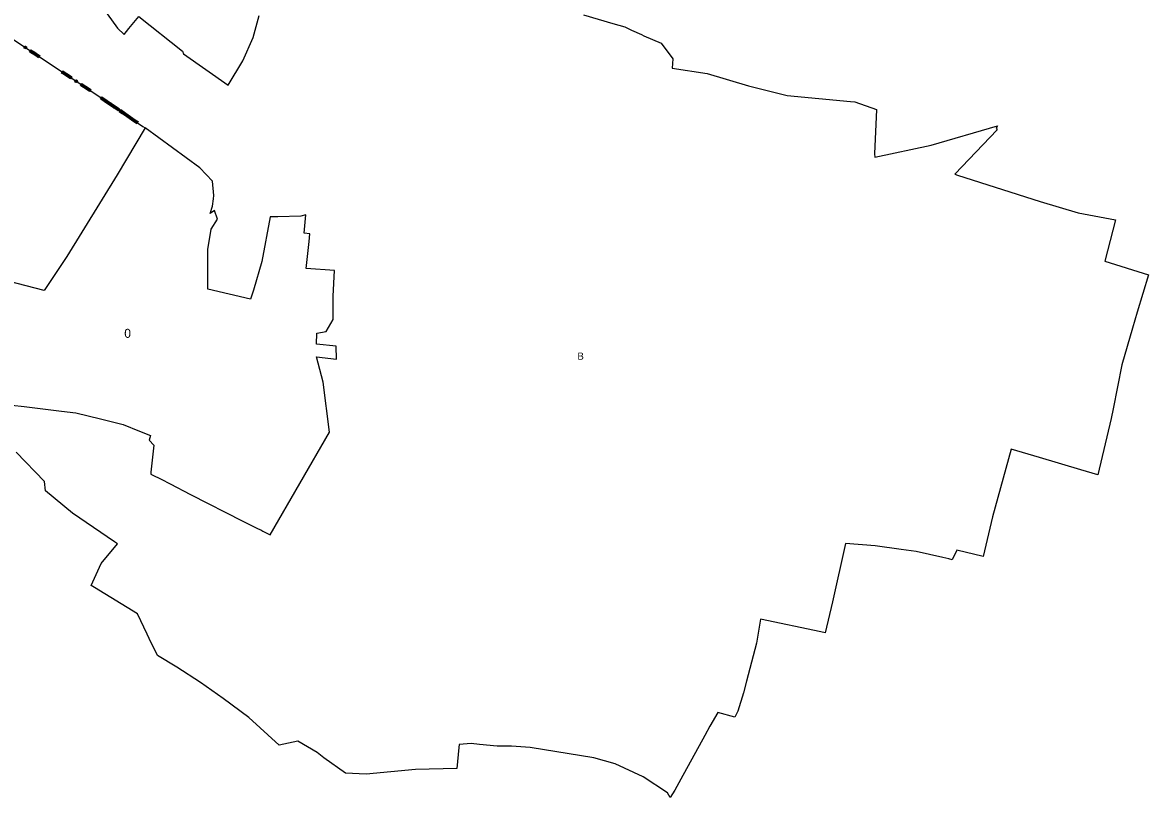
# Model space of a CAD drawing. Extents: x -648929 to -645777, y -1033280 to -1031329.
# Drawn here: x -647340 to -645777, y -1033280 to -1032204 of the extents above; entities that cross this region are included whole.
import ezdxf

# ---------------------------------------------------------------- set-up
doc = ezdxf.new("R2010")
doc.units = 0
for name, color, linetype in [('HRA_OK', 7, 'Continuous'), ('OVNE_SET', 7, 'Continuous'), ('OVNI_SET', 7, 'Continuous'), ('OZN', 7, 'Continuous'), ('POZN', 7, 'Continuous')]:
    doc.layers.add(name, color=color, linetype=linetype)

msp = doc.modelspace()

# ---------------------------------------------------------------- linework, layer by layer
at = {"layer": 'HRA_OK'}
for points in [[(-647363.4, -1032220.7), (-647238.5, -1032303.6), (-647172.9, -1032348.3), (-647169.7, -1032350.5)], [(-647335.9, -1032237), (-647334.8, -1032237.7), (-647334.6, -1032239), (-647335.3, -1032240.2), (-647336.6, -1032240.4), (-647337.7, -1032239.7), (-647338, -1032238.4), (-647337.3, -1032237.2), (-647335.9, -1032237), (-647336, -1032237.2), (-647335, -1032237.8), (-647334.9, -1032238.4), (-647336.6, -1032237.3), (-647337.1, -1032237.4), (-647334.8, -1032238.9), (-647335, -1032239.3), (-647337.3, -1032237.7), (-647337.6, -1032238.1), (-647335.2, -1032239.6), (-647335.5, -1032239.9), (-647337.8, -1032238.4), (-647337.7, -1032238.9), (-647336, -1032240), (-647336.6, -1032240.2), (-647337.6, -1032239.5)], [(-647328.4, -1032241.8), (-647323.2, -1032245.3), (-647317.9, -1032248.8), (-647316, -1032250.1), (-647317.9, -1032253), (-647323.2, -1032249.5), (-647328.5, -1032246), (-647330.4, -1032244.7), (-647328.4, -1032241.8), (-647328.3, -1032242.3), (-647323.1, -1032245.8), (-647317.8, -1032249.3), (-647316.4, -1032250.2), (-647316.6, -1032250.6), (-647321.9, -1032247), (-647327.2, -1032243.5), (-647328.6, -1032242.6), (-647328.8, -1032242.9), (-647323.5, -1032246.4), (-647318.2, -1032249.9), (-647316.8, -1032250.9), (-647317, -1032251.2), (-647322.3, -1032247.7), (-647327.6, -1032244.2), (-647329, -1032243.3), (-647329.2, -1032243.6), (-647323.9, -1032247.1), (-647318.7, -1032250.6), (-647317.2, -1032251.6), (-647317.5, -1032251.9), (-647322.7, -1032248.4), (-647328, -1032244.9), (-647329.5, -1032243.9), (-647329.7, -1032244.3), (-647324.4, -1032247.8), (-647319.1, -1032251.3), (-647317.7, -1032252.2), (-647317.9, -1032252.6), (-647323.2, -1032249), (-647328.5, -1032245.5), (-647329.9, -1032244.6)], [(-647284, -1032271.3), (-647278.7, -1032274.8), (-647273.4, -1032278.3), (-647271.5, -1032279.6), (-647273.4, -1032282.5), (-647278.7, -1032279), (-647284, -1032275.5), (-647285.9, -1032274.2), (-647284, -1032271.3), (-647283.9, -1032271.7), (-647278.6, -1032275.3), (-647273.4, -1032278.8), (-647271.9, -1032279.7), (-647272.2, -1032280), (-647277.5, -1032276.5), (-647282.7, -1032273), (-647284.2, -1032272.1), (-647284.4, -1032272.4), (-647279.1, -1032275.9), (-647273.8, -1032279.4), (-647272.4, -1032280.4), (-647272.6, -1032280.7), (-647277.9, -1032277.2), (-647283.2, -1032273.7), (-647284.6, -1032272.7), (-647284.8, -1032273.1), (-647279.5, -1032276.6), (-647274.2, -1032280.1), (-647272.8, -1032281), (-647273, -1032281.4), (-647278.3, -1032277.9), (-647283.6, -1032274.4), (-647285, -1032273.4), (-647285.3, -1032273.7), (-647280, -1032277.3), (-647274.7, -1032280.8), (-647273.3, -1032281.7), (-647273.5, -1032282), (-647278.8, -1032278.5), (-647284.1, -1032275), (-647285.5, -1032274.1)], [(-647265.2, -1032283.9), (-647264.1, -1032284.7), (-647263.8, -1032286), (-647264.6, -1032287.1), (-647265.9, -1032287.4), (-647267, -1032286.7), (-647267.3, -1032285.3), (-647266.5, -1032284.2), (-647265.2, -1032283.9), (-647265.3, -1032284.1), (-647264.3, -1032284.8), (-647264.2, -1032285.4), (-647265.8, -1032284.3), (-647266.4, -1032284.4), (-647264.1, -1032285.9), (-647264.3, -1032286.2), (-647266.6, -1032284.7), (-647266.8, -1032285), (-647264.5, -1032286.6), (-647264.7, -1032286.9), (-647267.1, -1032285.4), (-647266.9, -1032285.9), (-647265.3, -1032287), (-647265.8, -1032287.1), (-647266.8, -1032286.5)], [(-647257.7, -1032288.7), (-647252.4, -1032292.3), (-647247.1, -1032295.8), (-647245.2, -1032297), (-647247.2, -1032300), (-647252.4, -1032296.4), (-647257.7, -1032292.9), (-647259.6, -1032291.7), (-647257.7, -1032288.7), (-647257.6, -1032289.2), (-647252.3, -1032292.7), (-647247, -1032296.3), (-647245.6, -1032297.2), (-647245.8, -1032297.5), (-647251.1, -1032294), (-647256.4, -1032290.5), (-647257.8, -1032289.6), (-647258.1, -1032289.9), (-647252.8, -1032293.4), (-647247.5, -1032296.9), (-647246.1, -1032297.9), (-647246.3, -1032298.2), (-647251.6, -1032294.7), (-647256.9, -1032291.2), (-647258.3, -1032290.2), (-647258.5, -1032290.6), (-647253.2, -1032294.1), (-647247.9, -1032297.6), (-647246.5, -1032298.5), (-647246.7, -1032298.9), (-647252, -1032295.3), (-647257.3, -1032291.8), (-647258.7, -1032290.9), (-647258.9, -1032291.2), (-647253.7, -1032294.7), (-647248.4, -1032298.3), (-647246.9, -1032299.2), (-647247.2, -1032299.5), (-647252.5, -1032296), (-647257.7, -1032292.5), (-647259.2, -1032291.6)], [(-647229.9, -1032307.4), (-647224.6, -1032311), (-647219.4, -1032314.5), (-647217.5, -1032315.8), (-647219.4, -1032318.7), (-647224.7, -1032315.1), (-647229.9, -1032311.6), (-647231.8, -1032310.3), (-647229.9, -1032307.4), (-647229.8, -1032307.8), (-647224.6, -1032311.4), (-647219.3, -1032315), (-647217.9, -1032315.9), (-647218.2, -1032316.3), (-647223.4, -1032312.7), (-647228.7, -1032309.1), (-647230.1, -1032308.1), (-647230.3, -1032308.5), (-647225, -1032312.1), (-647219.8, -1032315.6), (-647218.4, -1032316.6), (-647218.6, -1032316.9), (-647223.9, -1032313.3), (-647229.1, -1032309.8), (-647230.5, -1032308.8), (-647230.7, -1032309.1), (-647225.5, -1032312.7), (-647220.2, -1032316.3), (-647218.8, -1032317.2), (-647219.1, -1032317.6), (-647224.3, -1032314), (-647229.6, -1032310.4), (-647231, -1032309.5), (-647231.2, -1032309.8), (-647225.9, -1032313.4), (-647220.7, -1032316.9), (-647219.3, -1032317.9), (-647219.5, -1032318.2), (-647224.8, -1032314.7), (-647230, -1032311.1), (-647231.4, -1032310.1)], [(-647218, -1032315.5), (-647212.7, -1032319.1), (-647207.5, -1032322.6), (-647205.6, -1032323.9), (-647207.5, -1032326.8), (-647212.8, -1032323.2), (-647218, -1032319.7), (-647219.9, -1032318.4), (-647218, -1032315.5), (-647218, -1032315.9), (-647212.7, -1032319.5), (-647207.5, -1032323.1), (-647206.1, -1032324), (-647206.3, -1032324.3), (-647211.5, -1032320.8), (-647216.8, -1032317.2), (-647218.2, -1032316.2), (-647218.4, -1032316.6), (-647213.2, -1032320.1), (-647207.9, -1032323.7), (-647206.5, -1032324.7), (-647206.7, -1032325), (-647212, -1032321.4), (-647217.2, -1032317.9), (-647218.6, -1032316.9), (-647218.9, -1032317.2), (-647213.6, -1032320.8), (-647208.4, -1032324.4), (-647207, -1032325.3), (-647207.2, -1032325.7), (-647212.4, -1032322.1), (-647217.7, -1032318.5), (-647219.1, -1032317.6), (-647219.3, -1032317.9), (-647214.1, -1032321.5), (-647208.8, -1032325), (-647207.4, -1032326), (-647207.6, -1032326.3), (-647212.9, -1032322.8), (-647218.1, -1032319.2), (-647219.5, -1032318.2)], [(-647211.3, -1032320.2), (-647210.1, -1032321), (-647209.9, -1032322.3), (-647210.7, -1032323.4), (-647212, -1032323.7), (-647213.1, -1032322.9), (-647213.3, -1032321.6), (-647212.6, -1032320.5), (-647211.3, -1032320.2), (-647211.3, -1032320.4), (-647210.3, -1032321.1), (-647210.2, -1032321.7), (-647211.9, -1032320.5), (-647212.4, -1032320.6), (-647210.1, -1032322.2), (-647210.4, -1032322.5), (-647212.7, -1032321), (-647212.9, -1032321.3), (-647210.6, -1032322.9), (-647210.8, -1032323.2), (-647213.1, -1032321.6), (-647213, -1032322.2), (-647211.4, -1032323.3), (-647211.9, -1032323.4), (-647212.9, -1032322.7)], [(-647203.8, -1032325.1), (-647198.6, -1032328.7), (-647193.3, -1032332.3), (-647191.4, -1032333.6), (-647193.4, -1032336.5), (-647198.6, -1032332.9), (-647203.9, -1032329.3), (-647205.8, -1032328), (-647203.8, -1032325.1), (-647203.7, -1032325.6), (-647198.5, -1032329.2), (-647193.2, -1032332.8), (-647191.8, -1032333.7), (-647192.1, -1032334), (-647197.3, -1032330.5), (-647202.5, -1032326.9), (-647204, -1032325.9), (-647204.2, -1032326.3), (-647198.9, -1032329.8), (-647193.7, -1032333.4), (-647192.3, -1032334.4), (-647192.5, -1032334.7), (-647197.8, -1032331.1), (-647203, -1032327.6), (-647204.4, -1032326.6), (-647204.6, -1032326.9), (-647199.4, -1032330.5), (-647194.1, -1032334.1), (-647192.7, -1032335), (-647193, -1032335.4), (-647198.2, -1032331.8), (-647203.5, -1032328.2), (-647204.9, -1032327.3), (-647205.1, -1032327.6), (-647199.8, -1032331.2), (-647194.6, -1032334.7), (-647193.2, -1032335.7), (-647193.4, -1032336), (-647198.7, -1032332.5), (-647203.9, -1032328.9), (-647205.3, -1032327.9)], [(-647199.4, -1032328.3), (-647198.3, -1032329.1), (-647198, -1032330.4), (-647198.8, -1032331.5), (-647200.1, -1032331.8), (-647201.2, -1032331), (-647201.5, -1032329.7), (-647200.7, -1032328.6), (-647199.4, -1032328.3), (-647199.5, -1032328.5), (-647198.5, -1032329.2), (-647198.4, -1032329.8), (-647200, -1032328.6), (-647200.6, -1032328.7), (-647198.3, -1032330.3), (-647198.5, -1032330.6), (-647200.8, -1032329.1), (-647201, -1032329.4), (-647198.7, -1032331), (-647198.9, -1032331.3), (-647201.2, -1032329.7), (-647201.1, -1032330.3), (-647199.5, -1032331.4), (-647200, -1032331.5), (-647201, -1032330.8)], [(-647191.9, -1032333.2), (-647186.7, -1032336.8), (-647181.4, -1032340.4), (-647179.5, -1032341.7), (-647181.5, -1032344.6), (-647186.8, -1032341), (-647192, -1032337.4), (-647193.9, -1032336.1), (-647191.9, -1032333.2), (-647191.9, -1032333.7), (-647186.6, -1032337.3), (-647181.4, -1032340.9), (-647180, -1032341.8), (-647180.2, -1032342.1), (-647185.4, -1032338.6), (-647190.7, -1032335), (-647192.1, -1032334), (-647192.3, -1032334.4), (-647187.1, -1032337.9), (-647181.8, -1032341.5), (-647180.4, -1032342.5), (-647180.6, -1032342.8), (-647185.9, -1032339.2), (-647191.1, -1032335.7), (-647192.5, -1032334.7), (-647192.8, -1032335), (-647187.5, -1032338.6), (-647182.3, -1032342.2), (-647180.9, -1032343.1), (-647181.1, -1032343.5), (-647186.3, -1032339.9), (-647191.6, -1032336.3), (-647193, -1032335.4), (-647193.2, -1032335.7), (-647188, -1032339.3), (-647182.7, -1032342.8), (-647181.3, -1032343.8), (-647181.5, -1032344.1), (-647186.8, -1032340.6), (-647192, -1032337), (-647193.4, -1032336)]]:
    msp.add_lwpolyline(points, dxfattribs=at)
at = {"layer": 'OVNE_SET'}
for points in [[(-646561.1, -1032193.6), (-646520.2, -1032205.5), (-646503.9, -1032210.3), (-646494.6, -1032214.5), (-646480.8, -1032220.8), (-646477.2, -1032222.4), (-646453.3, -1032232.9), (-646437.3, -1032254.4), (-646437.8, -1032267.7), (-646389.6, -1032275), (-646332.1, -1032292), (-646278.4, -1032305.5), (-646190.3, -1032313.6), (-646184.5, -1032314.1), (-646154.2, -1032324.9), (-646157.1, -1032386.4), (-646156.7, -1032391.1), (-646078.5, -1032374.5), (-645986.3, -1032347.7), (-645988.3, -1032350.8), (-645986.9, -1032353), (-646045.7, -1032414.9), (-646041.8, -1032416.3), (-645926.8, -1032452.8), (-645874, -1032468.5), (-645822.5, -1032478.1), (-645837.4, -1032535.5), (-645776.6, -1032554.6), (-645792.2, -1032606.2), (-645798.8, -1032628.7), (-645813.8, -1032679.3), (-645825.8, -1032740.4), (-645828.5, -1032754.1), (-645847, -1032832.1), (-645870.7, -1032825.1), (-645927.8, -1032808.2), (-645967.4, -1032796.4), (-645993.4, -1032890.7), (-646006, -1032945.7), (-646042.8, -1032936.7), (-646049.2, -1032950.1), (-646053.9, -1032949), (-646062.1, -1032947.2), (-646099.4, -1032938.8), (-646120.1, -1032935.8), (-646156, -1032930.7), (-646197.4, -1032927.8), (-646215.2, -1033008.8), (-646225.5, -1033051.8), (-646231.7, -1033050.4), (-646315.2, -1033032.9), (-646321.1, -1033065.8), (-646334.9, -1033118.9), (-646339, -1033134.8), (-646346.9, -1033160.4), (-646350.8, -1033168.8), (-646374.7, -1033162.2), (-646385.6, -1033181.3), (-646392.6, -1033194.3), (-646425.8, -1033254.9), (-646434.3, -1033270.3), (-646440.6, -1033280.3), (-646444.6, -1033273.7), (-646478.1, -1033251.7), (-646517.2, -1033233.4), (-646546.6, -1033225.3), (-646635.2, -1033210.7), (-646661, -1033209), (-646680.8, -1033209.1), (-646705.6, -1033206.6), (-646717.1, -1033205.5), (-646733.7, -1033206.9), (-646734.1, -1033210.9), (-646737.2, -1033240), (-646794.2, -1033241.5), (-646862.8, -1033248), (-646891.6, -1033246.7), (-646921.6, -1033225.3), (-646930.8, -1033217.8), (-646957.6, -1033202.2), (-646983.8, -1033207.9), (-647025.7, -1033169.1), (-647061.4, -1033142.7), (-647093.1, -1033120.8), (-647125.6, -1033099.3), (-647152.8, -1033083.3), (-647164.3, -1033059.4), (-647167.2, -1033053.6), (-647180.6, -1033025.3), (-647240.3, -1032988.9), (-647244.9, -1032986.1), (-647230.7, -1032955.6), (-647208.4, -1032927.9), (-647212.6, -1032925.4), (-647270.5, -1032885.7), (-647308.1, -1032854.7), (-647309.6, -1032841.7), (-647348.7, -1032800.6)], [(-647228.6, -1032183.6), (-647208.1, -1032212), (-647198.9, -1032220.6), (-647192.5, -1032212.6), (-647178.4, -1032195.6), (-647117.9, -1032243.7), (-647116.5, -1032247.8), (-647054.5, -1032291.2), (-647034.2, -1032257.2), (-647019.6, -1032225.1), (-647011.6, -1032194.3)]]:
    msp.add_lwpolyline(points, dxfattribs=at)
at = {"layer": 'OVNI_SET'}
msp.add_lwpolyline([(-647355, -1032735.7), (-647338, -1032737.5), (-647312, -1032740.8), (-647285.8, -1032743.8), (-647266.2, -1032746.3), (-647232, -1032754.5), (-647200.2, -1032762.2), (-647177.8, -1032771.8), (-647162.5, -1032777.7), (-647164.4, -1032784.3), (-647157.8, -1032791), (-647162.1, -1032828.7), (-647161.9, -1032831.5), (-647160.2, -1032832.2), (-647160, -1032832.3), (-647147.4, -1032838.4), (-647135, -1032844.9), (-647106.7, -1032859.7), (-647034.1, -1032896.8), (-647029.7, -1032898.9), (-647012.9, -1032907.2), (-647009.4, -1032908.7), (-647006.3, -1032910.5), (-647001.7, -1032912.7), (-646996, -1032915.5), (-646914, -1032772.9), (-646922.4, -1032703.7), (-646932, -1032668.6), (-646903.9, -1032671.8), (-646904.5, -1032653.6), (-646931.8, -1032650.7), (-646931.4, -1032635.4), (-646918.4, -1032633.1), (-646908.6, -1032616.3), (-646908.9, -1032584.1), (-646906.8, -1032548.7), (-646946.1, -1032545.8), (-646942.2, -1032508.2), (-646941.2, -1032497.7), (-646949.2, -1032496.8), (-646946.7, -1032471.2), (-646953.6, -1032472.8), (-646985.4, -1032474), (-646996.2, -1032474), (-647007.8, -1032536), (-647019.2, -1032576), (-647023.3, -1032588.5), (-647083, -1032574.6), (-647083, -1032519.1), (-647078.3, -1032491.2), (-647069.5, -1032477), (-647073.4, -1032465.3), (-647079.5, -1032469.1), (-647076.2, -1032459.3), (-647074.9, -1032448.9), (-647074.3, -1032444.4), (-647076.3, -1032424.2), (-647094.1, -1032405.7), (-647169.7, -1032350.5), (-647208.8, -1032415.4), (-647278.7, -1032529), (-647310.2, -1032576.3), (-647399.9, -1032552.9)], dxfattribs=at)

# ---------------------------------------------------------------- texts
at = {"layer": 'OZN'}
msp.add_text('0', height=12.5, dxfattribs=at).set_placement((-647198.8, -1032642))
at = {"layer": 'POZN'}
msp.add_text('B', height=10, dxfattribs=at).set_placement((-646569.6, -1032672.4))

doc.saveas('drawing.dxf')
